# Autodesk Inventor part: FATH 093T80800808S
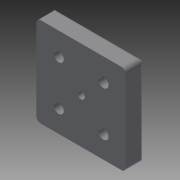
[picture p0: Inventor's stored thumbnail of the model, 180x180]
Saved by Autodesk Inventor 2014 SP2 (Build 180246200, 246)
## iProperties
Created: 2018-10
Part Number: FATH 093T80800808S
Material: Generic
Catalog Web Link: www.cadenas.de
Description: Transport and Base Plate 80 x 80-Die-cast Zinc
Vendor: FATH
Document SubType Name: Modeling
Designer: psadmin
Manufacturer: FATH
Mass: 92.9209 g
Surface Area: 196.252 cm^2
Volume: 92.9209 cm^3
Density: 1 g/cm^3
Appearance: PSOLRGB-175-175-175
Category: PARTsolutions
Company: FATH
Title: FATH 093T80800808S
Author: Cadenas PARTsolutions
Comments: Die-cast Zinc
PSOL_IDENT_0: {$CADENAS_DATA\23d-libs\fath\zubehoer_alu_sys\fussplatten\093t8080.prj},194 {VTYP=3D},{NB=FATH 093T8
PSOL_IDENT_1: 0800808S},{LINA=FATH 093T80800808S},{NN=Transport and Base Plate 80 x 80},{DATE=19.02.2018 15:31:06}
PSOL_IDENT_2: ,{GEOMDATE=26.05.2005},{VERSION=},{LINEID=570},{WBVAR=},{WBNUMERIC=}  {NB=FATH 093T80800808S},{LINA=
PSOL_IDENT_3: FATH 093T80800808S},{KT=DUMMY},{BO=für M8},{D=9.0},{DIM=80x80},{A=40},{M=M8},{O=pulverbeschichtet},{
PSOL_IDENT_4: ARTNR=093T80800808S},{PRTNO=},{L=80},{B=80},{H=16},{D1=9.0},{D2=15},{T=9.0},{GEW=8},{KD=6.5},{R1=4.0
PSOL_IDENT_5: },{R2=3},{FO=2}
NN: Transport- und Fußplatte 80x80
NT: Zinkdruckguss
NB: FATH 093T80800808S
NBSYN: FATH $ARTNR.
LINA: FATH 093T80800808S
BO: für M8
D: 9
DIM: 80x80
A: 40
M: M8
O: pulverbeschichtet
ARTNR: 093T80800808S
SUPPLIER: FATH
ARTICLENO: FATH 093T80800808S
BOMINFO: FATH 093T80800808S
CREATOR: CADENAS GmbH
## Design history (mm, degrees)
sketch "Skizze_1"
  geometry: L1 (36, 40)-(-36, 40); L2 (-40, 36)-(-40, -36); L3 (-36, -40)-(36, -40); L4 (40, -36)-(40, 36); A1 r 4 centre (36, 36) between (40, 36) and (36, 40); A2 r 4 centre (-36, 36) between (-36, 40) and (-40, 36); A3 r 4 centre (-36, -36) between (-40, -36) and (-36, -40); A4 r 4 centre (36, -36) between (36, -40) and (40, -36)
  constraints: 8 end point, 8 point on circle, 4 centre point
extrude "Extrusion1" join sketch "Skizze_1" distance "d0" = 16; taper "d1" = 0 deg
sketch "Skizze_2"
  geometry: L1 (19, 43)-(0, 43); L2 (0, 43)-(0, 40); L3 (0, 40)-(13, 40); L4 (16, 37)-(16, -37); L5 (13, -40)-(0, -40); L6 (0, -40)-(0, -43); L7 (0, -43)-(19, -43); L8 (19, -43)-(19, 43); A1 r 3 centre (13, 37) between (16, 37) and (13, 40); A2 r 3 centre (13, -37) between (13, -40) and (16, -37)
  constraints: 16 end point, 4 point on circle, 2 centre point
extrude "Extrusion2" cut sketch "Skizze_2" stored distance "d2" = 80; taper "d3" = 0 deg
sketch "Skizze_3"
  geometry: L1 (-43, 19)-(-43, 0); L2 (-43, 0)-(-40, 0); L3 (-40, 0)-(-40, 13); L4 (-37, 16)-(37, 16); L5 (40, 13)-(40, 0); L6 (40, 0)-(43, 0); L7 (43, 0)-(43, 19); L8 (43, 19)-(-43, 19); A1 r 3 centre (-37, 13) between (-37, 16) and (-40, 13); A2 r 3 centre (37, 13) between (40, 13) and (37, 16)
  constraints: 16 end point, 4 point on circle, 2 centre point
extrude "Extrusion3" cut sketch "Skizze_3" stored distance "d4" = 80; taper "d5" = 0 deg
sketch "Skizze_7"
  geometry: L1 (-20, 18)-(-20, 0); L2 (-20, 0)-(-24.5, 0); L3 (-24.5, 0)-(-24.5, 7); L4 (-24.5, 7)-(-27.5, 7); L5 (-27.5, 7)-(-27.5, 18); L6 (-27.5, 18)-(-20, 18); L7 (-20, 18)-(-20, 0)
  constraints: 14 end point
revolve "Revolution1" sketch "Skizze_7" stored, may be unused: angle "d6" = 360 deg
sketch "Skizze_8"
  geometry: L1 (20, 18)-(20, 0); L2 (20, 0)-(15.5, 0); L3 (15.5, 0)-(15.5, 7); L4 (15.5, 7)-(12.5, 7); L5 (12.5, 7)-(12.5, 18); L6 (12.5, 18)-(20, 18); L7 (20, 18)-(20, 0)
  constraints: 14 end point
revolve "Revolution2" sketch "Skizze_8" stored, may be unused: angle "d7" = 360 deg
sketch "Skizze_9"
  geometry: L1 (-20, 18)-(-20, 0); L2 (-20, 0)-(-24.5, 0); L3 (-24.5, 0)-(-24.5, 7); L4 (-24.5, 7)-(-27.5, 7); L5 (-27.5, 7)-(-27.5, 18); L6 (-27.5, 18)-(-20, 18); L7 (-20, 18)-(-20, 0)
  constraints: 14 end point
revolve "Revolution3" sketch "Skizze_9" stored, may be unused: angle "d8" = 360 deg
sketch "Skizze_10"
  geometry: L1 (20, 18)-(20, 0); L2 (20, 0)-(15.5, 0); L3 (15.5, 0)-(15.5, 7); L4 (15.5, 7)-(12.5, 7); L5 (12.5, 7)-(12.5, 18); L6 (12.5, 18)-(20, 18); L7 (20, 18)-(20, 0)
  constraints: 14 end point
revolve "Revolution4" sketch "Skizze_10" stored, may be unused: angle "d9" = 360 deg
sketch "Sketch8"
  geometry: 1 further point
hole "Hole1" sketch "Sketch8" at (0, 0) diameter "d10" = 6.5; stored, may be unused: countersink angle "d14" = 90 deg, drill point angle "d16" = 0 deg; dims "d11" = 6, "d12" = 4, "d13" = 2, "d15" = 16
body "Solid1"
